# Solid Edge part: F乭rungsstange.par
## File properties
Username: bmolnar
Dokumentum tartalom típus: 0
Author: bmolnar
Last saved by: bmolnar
Revision: 81
Sűrűség: 0,000 kg/m^3
Pontosság: 0,990
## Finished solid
Body 1: solid body, 8 faces, 7 edges, 1 vertex.
  Faces by surface: cone 4, cylinder 2, plane 2
  Edges by curve: circle 7
Bounding box of the edges (mm): 6.000 x 6.000 x 55.000, from (-3, -3, -40) to (3, 3, 15).
Cylindrical faces by radius (mm): R1.621 x1, R3 x1
Conical faces (half-angle, radius in mm at the cone's reference point): 45 deg R1.721 x1, 45 deg R2.9 x1, 45 deg R3 x1, 59 deg R0.8105 x1
Planar faces by outward normal: +z 1, -z 1
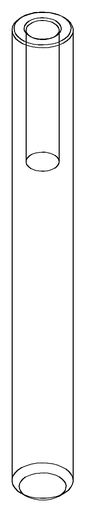
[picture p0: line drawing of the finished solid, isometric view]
